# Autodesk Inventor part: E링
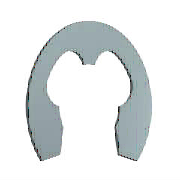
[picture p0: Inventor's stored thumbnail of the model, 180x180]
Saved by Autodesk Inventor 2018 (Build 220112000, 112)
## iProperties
Created: 2012-02
Part Number: E링
Material: 강철, 연강
Description: 스프링 리테이닝 링
Document SubType Name: Modeling
Standard: JIS B 2805
Designer: mduedu
Standards Organization: JIS
Language: ko-KR
Size Designation: 4
Categories: <MemberInstance><Categories><Category DisplayName="샤프트 부품" InternalName="7f7aeb1f-a693-4053-b835-cee3144e0d98" Mnemonic="SHFT"><Category DisplayName="써클립" Inter
Density: 1 g/cm^3
Appearance: 노란색
IsCustomPart: 1
Author: mduedu
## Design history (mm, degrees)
sketch "스케치1"
  geometry: L1 (-0.4, 0.024)-(0, 0.024) reference; L2 (-3.206, 0)-(3.486, 0) reference; L3 (-1.833, -3.276)-(1.833, -3.276); L4 (0, 1.949)-(0, -3.479) reference; L5 (-2.4, -1.676)-(-2.008, -1.676); L6 (-0.4, -0.076)-(-0.4, 0.312); L7 (0, 2.024)-(2.53, 2.024); L8 (-1.833, -3.276)-(-2.47, -5.119); L9 (0, -0.476)-(-1.278, -0.476); L10 (1.833, -3.276)-(2.47, -5.119); L11 (2.4, -1.676)-(2.008, -1.676); L12 (0.4, -0.076)-(0.4, 0.312); C1 r 2.5 at (0, -2.476); A1 r 2 centre (0, -2.476) between (-1.894, -1.835) and (-1.833, -3.276); A2 r 0.4 centre (0, -0.076) between (-0.4, -0.076) and (0.4, -0.076); A3 r 4.5 centre (0, -2.476) between (3.505, -5.299) and (-3.505, -5.299); A4 r 3.2 centre (0, -2.476) between (-0.8, 0.622) and (-2.824, -0.97); A5 r 0.32 centre (-0.72, 0.312) between (-0.4, 0.312) and (-0.8, 0.622); A6 r 0.48 centre (-2.4, -1.196) between (-2.824, -0.97) and (-2.4, -1.676); A7 r 0.12 centre (-2.008, -1.796) between (-1.894, -1.835) and (-2.008, -1.676); A8 r 0.6 centre (-3.037, -4.923) between (-3.505, -5.299) and (-2.47, -5.119); A9 r 0.6 centre (3.037, -4.923) between (2.47, -5.119) and (3.505, -5.299); A10 r 2 centre (0, -2.476) between (1.833, -3.276) and (1.894, -1.835); A11 r 0.12 centre (2.008, -1.796) between (2.008, -1.676) and (1.894, -1.835); A12 r 0.48 centre (2.4, -1.196) between (2.4, -1.676) and (2.824, -0.97); A13 r 3.2 centre (0, -2.476) between (2.824, -0.97) and (0.8, 0.622); A14 r 0.32 centre (0.72, 0.312) between (0.8, 0.622) and (0.4, 0.312); 1 further point
  constraints: 30 point on circle, 20 end point, 15 centre point, 13 symmetric about line, 12 tangent, 8 point on line, 4 parallel, 2 coincident, 2 horizontal, 1 concentric, 1 perpendicular, 1 vertical alignment, 9 other
  dimensions: "d0" = 5 diameter of C1 (= WD); "d3" = 0.8 distance from line of A1.centre L3 (= 0.2 x ND); "d4" = 0.4 radius of A2 (= 0.1 x ND); "d5" = 9 diameter of A3 (= SD2); "d8" = 3.2 radius of A4 (= 0.8 x ND); "d9" = 0.8 distance from line of A1.centre L5 (= 0.2 x ND); "d10" = 0.32 radius of A5 (= 0.08 x ND); "d11" = 0.48 radius of A6 (= 0.12 x ND); "d12" = 0.12 radius of A7 (= 0.03 x ND); "d13" = 0.6 radius of A8 (= 0.15 x ND); "d14" = 2 distance from line of A1.centre L9 (= 0.5 x ND); "d15" = 2 radius of A1 (= 0.5 x ND)
extrude "본체" new body sketch "스케치1" distance "d16" = 0.6 (= SD); taper "d17" = 0 deg
workaxis "Work Axis1"
workaxis "Work Axis2"
workplane "Work Plane1"
body "Solid1"
other parameters: "ND" = 4 [user parameter; used in 14 equation terms], "SD" = 0.6 [user parameter; used in 1 equation term], "WD" = 5 (= WDMIN) [user parameter; used in 1 equation term], "d1" = 6.4 (= 1.6 x ND), "d2" = 4 (= ND), "SD2" = 9 [user parameter; used in 1 equation term], "d6" = 4 (= ND), "d7" = 0.6 (= 0.15 x ND), "d18" = 0, "d19" = 0, "d27" = 0, "d28" = 0, "WDMIN" = 5 [user parameter; used in 1 equation term], "SNB" = 0.7 [user parameter], "WDMAX" = 7 [user parameter], "BUBRMI" = 1.2 [user parameter]
